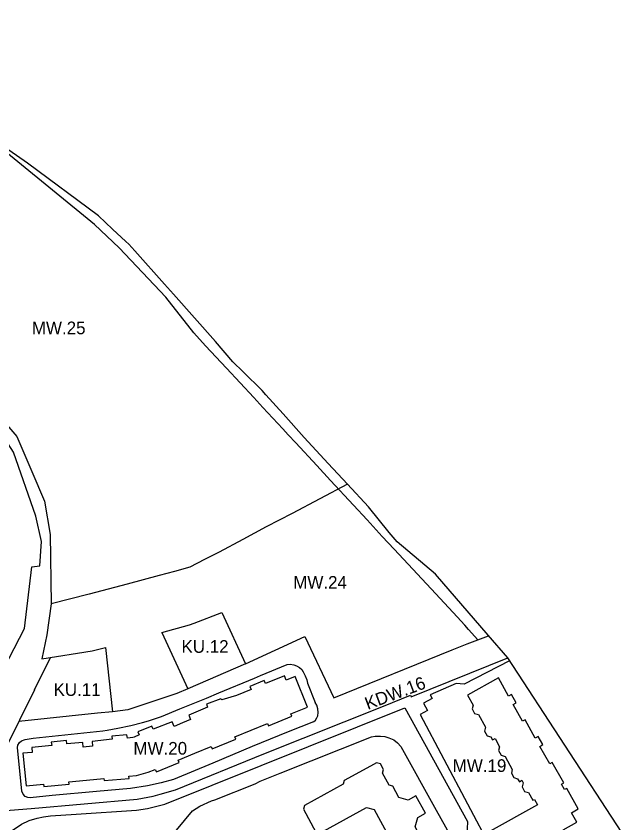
# Model space of a CAD drawing. Extents: x 7426178 to 7427732, y 5548847 to 5550287.
# Drawn here: x 7426953.6 to 7427168.7, y 5549707.1 to 5549993.4 of the extents above; entities that cross this region are included whole.
import ezdxf

# ---------------------------------------------------------------- set-up
doc = ezdxf.new("R2010")
doc.units = 0
for name, color, linetype in [('linie_rozgraniczajace', 7, 'Continuous'), ('linie_zabudowy_nieprzekraczalne', 7, 'Continuous'), ('linie_zabudowy_obowiazujace', 7, 'Continuous'), ('oznaczenia_przeznaczen', 7, 'Continuous')]:
    doc.layers.add(name, color=color, linetype=linetype)

msp = doc.modelspace()

# ---------------------------------------------------------------- linework, layer by layer
at = {"layer": 'linie_rozgraniczajace'}
for p, q in [((7426982.84, 5549922.53), (7426957.62, 5549941.24)), ((7426987.81, 5549917.87), (7426982.84, 5549922.53)), ((7426992.57, 5549913.49), (7426987.81, 5549917.87)), ((7427048.4, 5549852.24), (7427042.29, 5549859.05)), ((7427055.88, 5549843.91), (7427048.4, 5549852.24)), ((7427078.67, 5549819.24), (7427071.21, 5549827.25)), ((7427086.08, 5549810.15), (7427078.67, 5549819.24)), ((7427088.88, 5549806.79), (7427086.08, 5549810.15)), ((7427102.45, 5549795.3), (7427088.88, 5549806.79)), ((7427121.21, 5549773.66), (7427102.45, 5549795.3)), ((7427026.6, 5549781.7), (7427035.03, 5549763.47)), ((7427005.31, 5549774.7), (7427014.6, 5549754.61)), ((7427128.13, 5549765.67), (7427121.21, 5549773.66)), ((7426985.31, 5549769.35), (7426987.75, 5549746.44)), ((7426960.1, 5549754.29), (7426965.8, 5549765.79)), ((7427035.03, 5549763.47), (7427014.6, 5549754.61)), ((7427168.68, 5549703.66), (7427128.13, 5549765.67))]:
    msp.add_line(p, q, dxfattribs=at)
for points in [[(7426957.62, 5549941.24), (7426941.5, 5549952.34), (7426939.11, 5549953.98), (7426924.93, 5549964.83), (7426913.98, 5549973.04), (7426897.27, 5549985.34), (7426897.38, 5549985.5), (7426893.99, 5549988.01), (7426894.64, 5549988.87), (7426894.5, 5549988.97), (7426892.03, 5549990.78), (7426889.83, 5549992.35), (7426887.92, 5549993.43)], [(7427006.28, 5549898.33), (7426995.76, 5549910.11), (7426993.64, 5549912.49), (7426992.57, 5549913.49)], [(7427024.37, 5549877.91), (7427009.44, 5549894.77), (7427006.28, 5549898.33)], [(7426921.19, 5549708.68), (7426951.11, 5549765.58), (7426956.6, 5549776.07), (7426959.16, 5549797.97), (7426961.99, 5549798.27), (7426962.58, 5549807), (7426960.6, 5549815.99), (7426952.6, 5549838.71), (7426947.62, 5549846.2), (7426934.23, 5549863.11), (7426913.6, 5549887.98)], [(7426921.51, 5549886.93), (7426929.22, 5549876.25), (7426930.78, 5549874.24), (7426937.63, 5549865.37), (7426943.32, 5549856.38), (7426953.79, 5549844.23), (7426959.19, 5549831.83), (7426963.61, 5549821.24), (7426965.71, 5549809.49), (7426966.05, 5549784.81), (7426964.49, 5549773.85), (7426962.7, 5549765.31), (7426980.6, 5549768.08), (7426985.31, 5549769.35)], [(7427042.29, 5549859.05), (7427040.92, 5549860.57), (7427034.2, 5549867.13), (7427030.51, 5549870.72), (7427024.37, 5549877.91)], [(7427071.21, 5549827.25), (7427064.4, 5549834.68), (7427055.88, 5549843.91)], [(7427071.21, 5549827.25), (7427061.41, 5549822.05), (7427051.61, 5549816.85), (7427042.38, 5549812.18), (7427034.05, 5549807.69), (7427025.73, 5549803.2), (7427020.49, 5549800.51), (7427015.24, 5549797.83), (7427009.79, 5549796.34), (7427004.33, 5549794.85), (7426998.7, 5549793.31), (7426993.06, 5549791.77), (7426979.55, 5549788.29), (7426966.05, 5549784.81)], [(7427005.31, 5549774.7), (7427015.15, 5549777.33), (7427016.85, 5549777.98), (7427026.6, 5549781.7)], [(7427035.03, 5549763.47), (7427056.13, 5549773.23), (7427066.38, 5549751.45), (7427108.41, 5549768.48), (7427113.74, 5549770.63), (7427121.37, 5549773.48)], [(7426960.1, 5549754.29), (7426944.05, 5549721.95), (7426937.2, 5549708.62), (7426941.9, 5549709.19), (7426942.64, 5549710.57), (7426951.51, 5549711.54), (7426958.87, 5549712.14), (7426996.53, 5549715.51), (7427002.21, 5549716.59), (7427004.76, 5549717.21), (7427010.19, 5549718.81), (7427041.49, 5549731.55), (7427083.98, 5549748.53), (7427093.57, 5549752.35), (7427093.82, 5549751.76), (7427128.13, 5549765.67)], [(7427025.55, 5549753.23), (7427038.26, 5549758.47), (7427040.34, 5549759.34), (7427049.8, 5549763.31), (7427050.83, 5549763.37), (7427052.13, 5549763.22), (7427053.11, 5549762.87), (7427054.25, 5549762.22), (7427055.05, 5549761.5), (7427055.51, 5549760.71), (7427056.27, 5549759.22), (7427056.79, 5549757.82), (7427057.02, 5549756.69), (7427059.78, 5549749.77)], [(7427128.81, 5549764.62), (7427112.63, 5549756.3), (7427109.82, 5549756.54), (7427100.65, 5549752.52), (7427101.35, 5549751.27), (7427098.26, 5549749.58), (7427099.66, 5549747), (7427097.1, 5549745.56), (7427130.69, 5549682.07)], [(7427059.23, 5549742.96), (7427050.19, 5549739.35), (7427037.45, 5549734.14), (7427023.37, 5549728.27), (7427009.42, 5549722.51), (7427005.09, 5549721.26), (7427000.28, 5549720.21), (7426994.23, 5549719.3), (7426982.08, 5549718.2), (7426966.32, 5549716.77), (7426958.52, 5549715.97), (7426957.7, 5549716.07), (7426956.79, 5549716.49), (7426956.09, 5549717.23), (7426955.61, 5549718.27), (7426954, 5549733.78), (7426954.18, 5549734.68), (7426954.8, 5549735.55), (7426955.52, 5549736.14), (7426956.83, 5549736.66), (7426959.62, 5549737.12), (7426984.34, 5549739.79), (7426985.94, 5549740.02), (7426989.66, 5549740.65), (7426994.36, 5549741.67), (7426998.5, 5549742.73), (7427000.59, 5549743.33), (7427005.15, 5549744.86), (7427011.72, 5549747.58), (7427021.15, 5549751.38), (7427025.55, 5549753.23)], [(7427014.6, 5549754.61), (7427010.59, 5549752.95), (7426993.25, 5549747.25), (7426987.75, 5549746.44), (7426982.49, 5549746.07), (7426954.55, 5549743.11)], [(7427059.23, 5549742.96), (7427059.92, 5549743.58), (7427060.35, 5549744.3), (7427060.7, 5549745.08), (7427060.85, 5549746.3), (7427060.69, 5549747.6), (7427060.38, 5549748.81), (7427059.78, 5549749.77)], [(7426921.19, 5549708.68), (7426923.92, 5549704.82), (7426932.51, 5549700.17), (7426935.18, 5549699.15), (7426937.7, 5549698.72), (7426940.53, 5549698.67), (7426942.25, 5549698.99), (7426944.97, 5549699.87), (7426946.33, 5549700.48), (7426947.4, 5549701.24), (7426955.49, 5549706.64), (7426958.19, 5549707.88), (7426961.05, 5549708.75), (7426963.27, 5549709.23), (7426965.77, 5549709.6), (7426974.88, 5549710.13), (7426996.27, 5549711.61), (7427000.22, 5549712.16), (7427006.34, 5549713.7), (7427091.63, 5549747.86), (7427113.84, 5549707.59), (7427113.65, 5549702.41), (7427125.67, 5549680.75), (7427127, 5549680.04)], [(7426998.59, 5549690.1), (7427016.19, 5549711.38), (7427018.78, 5549713.04), (7427023, 5549714.89), (7427024.1, 5549715.21), (7427038.47, 5549720.92), (7427040.29, 5549721.88), (7427047.36, 5549724.73), (7427079.73, 5549737.66), (7427081.11, 5549737.9), (7427082.95, 5549737.9), (7427084.55, 5549737.72), (7427085.91, 5549737.31), (7427087.7, 5549736.5), (7427088.98, 5549735.46), (7427090.18, 5549734.17), (7427102.74, 5549711.55), (7427113.31, 5549692.82)]]:
    msp.add_lwpolyline(points, dxfattribs=at)
at = {"layer": 'linie_zabudowy_nieprzekraczalne'}
msp.add_line((7426981.22, 5549919.75), (7426981.22, 5549919.75), dxfattribs=at)
msp.add_lwpolyline([(7427117.51, 5549772.04), (7427114.27, 5549775.74), (7427112.91, 5549777.22), (7427110.2, 5549780.18), (7427102.57, 5549788.42), (7427089.44, 5549802.49), (7427087.77, 5549804.26), (7427083.6, 5549808.78), (7427078.22, 5549814.59), (7427073.36, 5549819.85), (7427065.22, 5549828.57), (7427060.3, 5549833.87), (7427052.86, 5549841.94), (7427050.17, 5549844.85), (7427048.25, 5549846.89), (7427041.23, 5549854.46), (7427037.99, 5549858.02), (7427028.29, 5549868.43), (7427020.87, 5549876.4), (7427016.68, 5549880.97), (7427006.68, 5549893.62), (7426990.15, 5549911.24), (7426985.79, 5549915.38), (7426981.43, 5549919.51), (7426939.19, 5549953.93)], dxfattribs=at)
at = {"layer": 'linie_zabudowy_obowiazujace'}
for p, q in [((7427031.84, 5549752.31), (7427026.58, 5549750.7)), ((7427037.02, 5549739.96), (7427042.81, 5549742.33)), ((7427078.05, 5549712.58), (7427080.73, 5549711.8)), ((7427080.73, 5549711.8), (7427085.96, 5549702.29))]:
    msp.add_line(p, q, dxfattribs=at)
for points in [[(7427042.81, 5549742.33), (7427043.16, 5549741.49), (7427051.5, 5549744.9), (7427051.15, 5549745.73), (7427057.08, 5549748.15), (7427052.64, 5549759.03), (7427049.49, 5549757.73), (7427048.86, 5549759.26), (7427042.18, 5549756.5), (7427041.71, 5549757.6), (7427036.62, 5549755.47), (7427037.09, 5549754.42), (7427031.84, 5549752.31)], [(7427147.81, 5549704.55), (7427152.74, 5549707.32), (7427150.8, 5549710.67), (7427153.19, 5549712), (7427149.12, 5549719.31), (7427148.33, 5549718.88), (7427147.26, 5549720.8), (7427148.07, 5549721.25), (7427143.9, 5549728.5), (7427143.04, 5549728), (7427139.57, 5549734.24), (7427140.58, 5549734.87), (7427138.96, 5549737.79), (7427137.93, 5549737.18), (7427134.3, 5549743.65), (7427133.44, 5549743.15), (7427130.1, 5549749.07), (7427131.13, 5549749.67), (7427129.47, 5549752.64), (7427128.44, 5549752.03), (7427124.82, 5549758.52), (7427113.89, 5549752.37), (7427115.86, 5549748.91)], [(7427026.58, 5549750.7), (7427026.23, 5549751.16), (7427021.14, 5549749.22), (7427021.56, 5549748.1), (7427014.88, 5549745.32), (7427015.54, 5549743.75), (7427012.6, 5549742.53)], [(7427115.86, 5549748.91), (7427115.46, 5549747.56), (7427116.38, 5549745.92), (7427117.73, 5549745.53), (7427120.27, 5549740.99), (7427119.91, 5549739.65), (7427120.81, 5549737.97), (7427122.18, 5549737.58), (7427122.77, 5549736.53), (7427123.64, 5549737.03), (7427125.27, 5549734.07), (7427124.9, 5549732.74), (7427125.85, 5549731.08), (7427127.22, 5549730.63), (7427129.76, 5549726.04), (7427129.46, 5549724.66), (7427130.32, 5549723.12), (7427131.66, 5549722.71), (7427132.27, 5549721.69), (7427133.11, 5549722.19), (7427133.66, 5549721.24), (7427133.26, 5549719.9), (7427134.16, 5549718.24), (7427135.48, 5549717.84), (7427137.08, 5549715.12), (7427137.6, 5549715.42), (7427138.71, 5549713.53), (7427121.95, 5549704.07)], [(7427012.6, 5549742.53), (7427009.67, 5549741.32), (7427009.02, 5549742.95), (7427002.28, 5549740.29), (7427001.78, 5549741.37), (7426996.8, 5549739.37), (7426997.23, 5549738.27), (7426995.43, 5549737.55), (7426995.03, 5549737.4), (7426993.07, 5549737.12), (7426992.93, 5549738.32), (7426987.56, 5549737.84), (7426987.65, 5549736.73), (7426980.53, 5549735.98), (7426980.71, 5549734.28), (7426977.42, 5549733.96), (7426977.26, 5549735.65), (7426971.62, 5549735.12), (7426971.49, 5549736.32), (7426966.07, 5549735.75), (7426966.2, 5549734.59), (7426959.1, 5549733.81), (7426959.24, 5549732.09), (7426955.96, 5549731.79), (7426957.08, 5549720.24), (7426963.3, 5549720.82), (7426963.38, 5549719.96), (7426972.4, 5549720.76), (7426972.32, 5549721.69), (7426978.52, 5549722.28), (7426984.74, 5549722.85), (7426984.83, 5549722.07), (7426993.72, 5549722.85), (7426993.65, 5549723.63), (7426996.3, 5549723.86), (7427000.44, 5549725.04), (7427003, 5549726.06), (7427003.4, 5549725.19), (7427011.49, 5549728.48), (7427011.07, 5549729.38), (7427017.05, 5549731.81)], [(7427017.05, 5549731.81), (7427022.88, 5549734.19), (7427023.22, 5549733.36), (7427031.56, 5549736.77), (7427031.22, 5549737.59), (7427037.02, 5549739.96)], [(7427100.74, 5549695.68), (7427095.24, 5549705.69), (7427096.19, 5549708.97), (7427098.93, 5549710.48), (7427095.52, 5549716.66), (7427092.78, 5549715.15), (7427089.49, 5549716.11), (7427087.3, 5549720.1), (7427086.08, 5549720.45), (7427083.71, 5549724.74), (7427084.07, 5549725.96), (7427082.96, 5549727.98), (7427081.56, 5549728.39), (7427079.41, 5549727.21), (7427070.08, 5549722.07), (7427069.73, 5549720.84), (7427055.97, 5549713.28), (7427055.57, 5549711.88), (7427060.01, 5549703.82), (7427061.41, 5549703.42), (7427062.67, 5549704.11), (7427078.05, 5549712.58)]]:
    msp.add_lwpolyline(points, dxfattribs=at)

# ---------------------------------------------------------------- texts
at = {"layer": 'oznaczenia_przeznaczen'}
for s, p in [('MW.25', (7426959.16, 5549880.52)), ('MW.24', (7427051.98, 5549790.19)), ('KU.12', (7427012.3, 5549767.43)), ('KU.11', (7426966.86, 5549752.14)), ('MW.20', (7426995.23, 5549731.29)), ('MW.19', (7427108.6, 5549725.14))]:
    msp.add_text(s, height=4.5, dxfattribs=at).set_placement(p)
msp.add_text('KDW.16', height=4.5, rotation=20.4816, dxfattribs=at).set_placement((7427078.43, 5549747.13))

doc.saveas('drawing.dxf')
